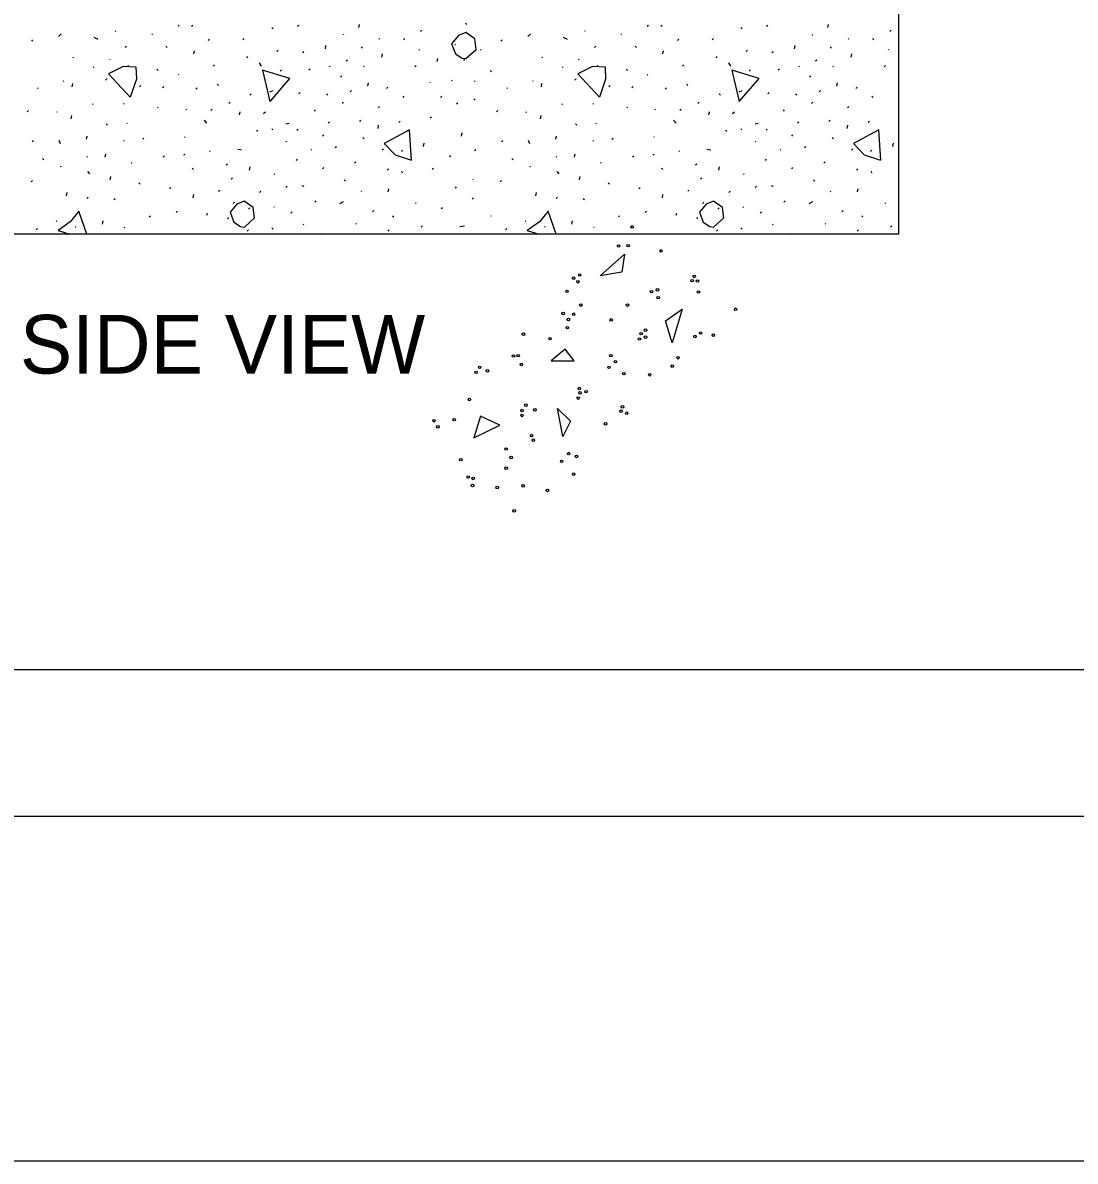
# Model space of a CAD drawing. Extents: x -120.7 to -50.3, y -20.2 to 3.8.
# Drawn here: x -68.476 to -64.887, y -20.241 to -16.36 of the extents above; entities that cross this region are included whole.
import ezdxf

# ---------------------------------------------------------------- set-up
doc = ezdxf.new("R2010")
doc.units = 0
for name, color, linetype in [('Default', 7, 'Continuous'), ('HATCH', 7, 'Continuous'), ('PR_Pattern_Area', 7, 'Continuous'), ('SHT_Plot_Shape_Full', 7, 'Continuous'), ('SHT_Plot_Shape_Half', 7, 'Continuous'), ('SHT_Sheet_Border', 7, 'Continuous'), ('TYP_Typical_Section_Linework', 7, 'Continuous'), ('TYP_Typical_Section_Txt', 7, 'Continuous')]:
    doc.layers.add(name, color=color, linetype=linetype)

# ---------------------------------------------------------------- blocks, each defined once
blk = doc.blocks.new('MCONC_1')
at = {"layer": 'Default'}
for points in [[(0.6469, 0.3145), (0.5681, 0.2555), (0.4697, 0.3244)], [(-0.5247, 0.2457), (-0.633, 0.1866), (-0.4853, 0.1374)], [(-0.0423, 0.1866), (0.0463, 0.0981), (0.0562, 0.1768)], [(-0.2884, -0.1479), (-0.1998, -0.02), (-0.1998, -0.1184)], [(0.6567, -0.1184), (0.4894, -0.2069), (0.5484, -0.0987)]]:
    blk.add_lwpolyline(points, close=True, dxfattribs=at)
for centre in [(-0.3736, 0.4299), (-0.3411, 0.4353), (-0.7283, 0.3677), (-0.7201, 0.4055), (-0.3248, 0.392), (-0.046, 0.3947), (0.2843, 0.392), (0.3601, 0.4164), (0.3629, 0.3866), (0.3953, 0.4055), (0.6553, 0.3677), (0.7798, 0.3893), (-0.6389, 0.3325), (-0.5035, 0.3514), (-0.1678, 0.3487), (-0.1489, 0.3325), (0.1842, 0.3217), (0.6932, 0.3325), (-0.1705, 0.2865), (0.038, 0.2757), (0.1463, 0.2513), (0.1815, 0.2784), (0.2221, 0.2784), (0.2843, 0.2865), (0.7988, 0.1864), (-0.7662, 0.1539), (-0.8041, 0.0592), (-0.3627, 0.089), (-0.3438, 0.1079), (-0.3086, 0.1133), (-0.2924, 0.0619), (0.3439, 0.1133), (0.463, 0.1079), (0.6065, 0.0673), (-0.8203, 0.0105), (-0.7905, 0.0348), (-0.5523, 0.0213), (0.6092, 0.0186), (0.6363, 0.0511), (-0.6254, -0.0517), (-0.5658, -0.0301), (-0.4142, -0.049), (-0.4034, -0.0247), (-0.0812, -0.0599), (-0.0541, -0.0463), (-0.0406, -0.0274), (-0.027, -0.0653), (0.1544, -0.0599), (0.2004, -0.0626), (0.2058, -0.022), (0.3791, -0.068), (0.4062, -0.0544), (0.436, -0.0572), (0.8042, -0.0463), (0.8231, -0.068), (0.8285, -0.0382), (-0.7337, -0.0923), (0.4089, -0.0842), (0.7852, -0.114), (-0.6281, -0.1843), (0.1869, -0.141), (-0.758, -0.2466), (-0.3871, -0.2384), (-0.3303, -0.2357), (0.2816, -0.2439), (-0.5523, -0.2953), (-0.3113, -0.2763), (-0.0758, -0.2628), (0.0325, -0.2736), (0.0461, -0.3034), (0.0542, -0.2628), (0.4008, -0.298), (0.4549, -0.2871), (0.6011, -0.2709), (0.6363, -0.279), (-0.3898, -0.3331), (0.6769, -0.3358), (0.861, -0.3223)]:
    blk.add_circle(centre, 0.00696, dxfattribs=at)

msp = doc.modelspace()

# ---------------------------------------------------------------- linework, layer by layer
at = {"layer": 'PR_Pattern_Area'}
for p, q in [((-67.9468, -16.3719), (-67.9424, -16.3675)), ((-67.9008, -16.3719), (-67.8964, -16.3675)), ((-67.6271, -16.3763), (-67.6227, -16.3807)), ((-67.5396, -16.3719), (-67.5352, -16.3675)), ((-67.3294, -16.3653), (-67.3316, -16.3762)), ((-66.966, -16.3609), (-66.9616, -16.3653)), ((-66.3468, -16.3719), (-66.3424, -16.3675)), ((-66.3008, -16.3719), (-66.2964, -16.3675)), ((-66.0271, -16.3763), (-66.0227, -16.3807)), ((-65.9396, -16.3719), (-65.9352, -16.3675)), ((-65.7294, -16.3653), (-65.7316, -16.3762)), ((-68.4457, -16.4222), (-68.4413, -16.4178)), ((-68.3538, -16.4069), (-68.3451, -16.3981)), ((-68.2334, -16.4091), (-68.2203, -16.4157)), ((-68.1591, -16.3872), (-68.1612, -16.3894)), ((-68.0343, -16.3981), (-68.0364, -16.4003)), ((-67.8439, -16.42), (-67.8395, -16.4156)), ((-67.7257, -16.4179), (-67.7213, -16.4135)), ((-67.382, -16.4003), (-67.3841, -16.4025)), ((-67.2594, -16.4135), (-67.2616, -16.4157)), ((-67.1784, -16.4135), (-67.174, -16.4179)), ((-67.1194, -16.3894), (-67.115, -16.385)), ((-66.8457, -16.4222), (-66.8413, -16.4178)), ((-66.7538, -16.4069), (-66.7451, -16.3981)), ((-66.6334, -16.4091), (-66.6203, -16.4157)), ((-66.5591, -16.3872), (-66.5612, -16.3894)), ((-66.4343, -16.3981), (-66.4364, -16.4003)), ((-66.2439, -16.42), (-66.2395, -16.4156)), ((-66.1257, -16.4179), (-66.1213, -16.4135)), ((-65.782, -16.4003), (-65.7841, -16.4025)), ((-65.6594, -16.4135), (-65.6616, -16.4157)), ((-65.5784, -16.4135), (-65.574, -16.4179)), ((-65.5194, -16.3894), (-65.515, -16.385)), ((-68.1263, -16.4441), (-68.1219, -16.4397)), ((-67.9882, -16.4397), (-67.9838, -16.4441)), ((-67.892, -16.455), (-67.8942, -16.4659)), ((-67.6097, -16.4573), (-67.6053, -16.4529)), ((-67.5221, -16.4616), (-67.5177, -16.4572)), ((-67.4433, -16.4375), (-67.4454, -16.4485)), ((-67.3228, -16.4419), (-67.3184, -16.4463)), ((-67.1237, -16.4507), (-67.1258, -16.4529)), ((-67.0011, -16.4332), (-67.0032, -16.4354)), ((-66.9136, -16.4507), (-66.9157, -16.4529)), ((-66.5263, -16.4441), (-66.5219, -16.4397)), ((-66.3882, -16.4397), (-66.3838, -16.4441)), ((-66.292, -16.455), (-66.2942, -16.4659)), ((-66.0097, -16.4573), (-66.0053, -16.4529)), ((-65.9221, -16.4616), (-65.9177, -16.4572)), ((-65.8433, -16.4375), (-65.8454, -16.4485)), ((-65.7228, -16.4419), (-65.7184, -16.4463)), ((-65.5237, -16.4507), (-65.5258, -16.4529)), ((-68.3036, -16.477), (-68.3057, -16.4792)), ((-68.1788, -16.4835), (-68.1809, -16.4857)), ((-67.7126, -16.4791), (-67.7082, -16.4747)), ((-67.3732, -16.4901), (-67.3688, -16.4857)), ((-67.2506, -16.466), (-67.2528, -16.4769)), ((-67.0624, -16.4813), (-67.0646, -16.4922)), ((-66.9727, -16.4879), (-66.9683, -16.4835)), ((-66.7036, -16.477), (-66.7057, -16.4792)), ((-66.5788, -16.4835), (-66.5809, -16.4857)), ((-66.1126, -16.4791), (-66.1082, -16.4747)), ((-65.7732, -16.4901), (-65.7688, -16.4857)), ((-65.6506, -16.466), (-65.6528, -16.4769)), ((-68.2335, -16.5098), (-68.2356, -16.512)), ((-68.1153, -16.5054), (-68.1174, -16.5076)), ((-68.0189, -16.5185), (-68.0145, -16.5229)), ((-67.8264, -16.5076), (-67.822, -16.5032)), ((-67.6621, -16.5076), (-67.6687, -16.4967)), ((-67.5986, -16.5251), (-67.5943, -16.5207)), ((-67.5002, -16.5207), (-67.4958, -16.5163)), ((-67.428, -16.5076), (-67.4301, -16.5098)), ((-67.312, -16.5076), (-67.3141, -16.5098)), ((-67.139, -16.5098), (-67.1346, -16.5054)), ((-66.8828, -16.5229), (-66.8784, -16.5273)), ((-66.6335, -16.5098), (-66.6356, -16.512)), ((-66.5153, -16.5054), (-66.5174, -16.5076)), ((-66.4189, -16.5185), (-66.4145, -16.5229)), ((-66.2264, -16.5076), (-66.222, -16.5032)), ((-66.0621, -16.5076), (-66.0687, -16.4967)), ((-65.9986, -16.5251), (-65.9943, -16.5207)), ((-65.9002, -16.5207), (-65.8958, -16.5163)), ((-65.828, -16.5076), (-65.8301, -16.5098)), ((-65.712, -16.5076), (-65.7141, -16.5098)), ((-65.539, -16.5098), (-65.5346, -16.5054)), ((-68.3364, -16.5579), (-68.3385, -16.5601)), ((-68.3079, -16.5777), (-68.3057, -16.5667)), ((-68.1941, -16.5557), (-68.1897, -16.5513)), ((-68.0781, -16.5777), (-68.0737, -16.5733)), ((-67.9446, -16.5361), (-67.9467, -16.5383)), ((-67.8132, -16.5689), (-67.8088, -16.5733)), ((-67.393, -16.5448), (-67.3886, -16.5404)), ((-67.2988, -16.5645), (-67.301, -16.5754)), ((-67.0865, -16.5623), (-67.0886, -16.5645)), ((-67.012, -16.5558), (-67.0142, -16.558)), ((-66.9332, -16.5579), (-66.9354, -16.5601)), ((-66.7364, -16.5579), (-66.7385, -16.5601)), ((-66.7079, -16.5777), (-66.7057, -16.5667)), ((-66.5941, -16.5557), (-66.5897, -16.5513)), ((-66.4781, -16.5777), (-66.4737, -16.5733)), ((-66.3446, -16.5361), (-66.3467, -16.5383)), ((-66.2132, -16.5689), (-66.2088, -16.5733)), ((-65.793, -16.5448), (-65.7886, -16.5404)), ((-65.6988, -16.5645), (-65.701, -16.5754)), ((-68.4238, -16.5821), (-68.426, -16.5843)), ((-67.9993, -16.582), (-67.9949, -16.5776)), ((-67.8855, -16.5864), (-67.8811, -16.582)), ((-67.7015, -16.6017), (-67.6971, -16.6061)), ((-67.6337, -16.5951), (-67.6227, -16.5908)), ((-67.5352, -16.6017), (-67.5308, -16.5973)), ((-67.441, -16.6017), (-67.4366, -16.6061)), ((-67.3601, -16.5951), (-67.3557, -16.5907)), ((-67.2354, -16.5842), (-67.231, -16.5798)), ((-67.1806, -16.6105), (-67.1762, -16.6149)), ((-67.0515, -16.6149), (-67.0471, -16.6105)), ((-66.8238, -16.5821), (-66.826, -16.5843)), ((-66.3993, -16.582), (-66.3949, -16.5776)), ((-66.2855, -16.5864), (-66.2811, -16.582)), ((-66.1015, -16.6017), (-66.0971, -16.6061)), ((-66.0337, -16.5951), (-66.0227, -16.5908)), ((-65.9352, -16.6017), (-65.9308, -16.5973)), ((-65.841, -16.6017), (-65.8366, -16.6061)), ((-65.7601, -16.5951), (-65.7557, -16.5907)), ((-65.6354, -16.5842), (-65.631, -16.5798)), ((-65.5806, -16.6105), (-65.5762, -16.6149)), ((-68.2357, -16.6367), (-68.2378, -16.6389)), ((-68.1306, -16.6346), (-68.1328, -16.6368)), ((-68.0146, -16.6477), (-68.0168, -16.6499)), ((-67.7738, -16.6345), (-67.7694, -16.6301)), ((-67.3864, -16.6345), (-67.382, -16.6301)), ((-67.2638, -16.6499), (-67.2594, -16.6455)), ((-66.9968, -16.6367), (-66.9924, -16.6323)), ((-66.9376, -16.6192), (-66.9332, -16.6236)), ((-66.6357, -16.6367), (-66.6378, -16.6389)), ((-66.5306, -16.6346), (-66.5328, -16.6368)), ((-66.4146, -16.6477), (-66.4168, -16.6499)), ((-66.1738, -16.6345), (-66.1694, -16.6301)), ((-65.7864, -16.6345), (-65.782, -16.6301)), ((-65.6638, -16.6499), (-65.6594, -16.6455)), ((-68.461, -16.663), (-68.4566, -16.6586)), ((-68.3583, -16.663), (-68.3604, -16.6652)), ((-68.3101, -16.6761), (-68.3122, -16.6871)), ((-67.9183, -16.6543), (-67.9204, -16.6565)), ((-67.8352, -16.6586), (-67.8308, -16.6542)), ((-67.7366, -16.6739), (-67.7344, -16.663)), ((-67.6556, -16.6696), (-67.649, -16.663)), ((-67.4827, -16.6608), (-67.4783, -16.6564)), ((-67.0865, -16.6849), (-67.0821, -16.6805)), ((-66.861, -16.663), (-66.8566, -16.6586)), ((-66.7583, -16.663), (-66.7604, -16.6652)), ((-66.7101, -16.6761), (-66.7122, -16.6871)), ((-66.3183, -16.6543), (-66.3204, -16.6565)), ((-66.2352, -16.6586), (-66.2308, -16.6542)), ((-66.1366, -16.6739), (-66.1344, -16.663)), ((-66.0556, -16.6696), (-66.049, -16.663)), ((-65.8827, -16.6608), (-65.8783, -16.6564)), ((-68.1918, -16.7046), (-68.1874, -16.709)), ((-68.1197, -16.7024), (-68.1218, -16.7046)), ((-67.8482, -16.7024), (-67.857, -16.6915)), ((-67.6796, -16.7265), (-67.6752, -16.7309)), ((-67.6271, -16.7199), (-67.6249, -16.7243)), ((-67.579, -16.7046), (-67.568, -16.7024)), ((-67.5418, -16.7265), (-67.5374, -16.7221)), ((-67.4346, -16.7024), (-67.4302, -16.698)), ((-67.3273, -16.6959), (-67.3229, -16.6915)), ((-67.2638, -16.7089), (-67.2659, -16.7199)), ((-67.1938, -16.7002), (-67.1894, -16.6958)), ((-66.5918, -16.7046), (-66.5874, -16.709)), ((-66.5197, -16.7024), (-66.5218, -16.7046)), ((-66.2482, -16.7024), (-66.257, -16.6915)), ((-66.0796, -16.7265), (-66.0752, -16.7309)), ((-66.0271, -16.7199), (-66.0249, -16.7243)), ((-65.979, -16.7046), (-65.968, -16.7024)), ((-65.9418, -16.7265), (-65.9374, -16.7221)), ((-65.8346, -16.7024), (-65.8302, -16.698)), ((-65.7273, -16.6959), (-65.7229, -16.6915)), ((-65.6638, -16.7089), (-65.6659, -16.7199)), ((-65.5938, -16.7002), (-65.5894, -16.6958)), ((-68.4435, -16.7659), (-68.4391, -16.7615)), ((-68.3472, -16.7724), (-68.3516, -16.7615)), ((-68.2576, -16.7461), (-68.2597, -16.7571)), ((-68.1306, -16.7615), (-68.1328, -16.7637)), ((-68.0672, -16.7571), (-68.0628, -16.7527)), ((-67.9227, -16.7484), (-67.9248, -16.7506)), ((-67.5768, -16.7659), (-67.579, -16.7637)), ((-67.4542, -16.7462), (-67.4498, -16.7418)), ((-67.3163, -16.7506), (-67.3119, -16.755)), ((-66.9792, -16.7353), (-66.9813, -16.7462)), ((-66.8435, -16.7659), (-66.8391, -16.7615)), ((-66.7472, -16.7724), (-66.7516, -16.7615)), ((-66.6576, -16.7461), (-66.6597, -16.7571)), ((-66.5306, -16.7615), (-66.5328, -16.7637)), ((-66.4672, -16.7571), (-66.4628, -16.7527)), ((-66.3227, -16.7484), (-66.3248, -16.7506)), ((-65.9768, -16.7659), (-65.979, -16.7637)), ((-65.8542, -16.7462), (-65.8498, -16.7418)), ((-65.7163, -16.7506), (-65.7119, -16.755)), ((-67.8373, -16.7965), (-67.8394, -16.7987)), ((-67.73, -16.7943), (-67.7431, -16.7921)), ((-67.4914, -16.7922), (-67.4936, -16.7944)), ((-67.4105, -16.7856), (-67.4061, -16.7812)), ((-67.2507, -16.7943), (-67.2463, -16.7899)), ((-67.185, -16.7987), (-67.1806, -16.7943)), ((-67.1084, -16.7703), (-67.1105, -16.7812)), ((-66.9354, -16.7965), (-66.931, -16.7921)), ((-66.2373, -16.7965), (-66.2394, -16.7987)), ((-66.13, -16.7943), (-66.1431, -16.7921)), ((-65.8914, -16.7922), (-65.8936, -16.7944)), ((-65.8105, -16.7856), (-65.8061, -16.7812)), ((-65.6507, -16.7943), (-65.6463, -16.7899)), ((-65.585, -16.7987), (-65.5806, -16.7943)), ((-65.5084, -16.7703), (-65.5105, -16.7812)), ((-68.4084, -16.8228), (-68.404, -16.8272)), ((-68.2554, -16.8163), (-68.2575, -16.8185)), ((-68.1941, -16.8075), (-68.1962, -16.8184)), ((-68.1044, -16.8359), (-68.1065, -16.8381)), ((-67.9971, -16.8184), (-67.9927, -16.814)), ((-67.927, -16.8097), (-67.9226, -16.8075)), ((-67.7826, -16.8447), (-67.7782, -16.8403)), ((-67.544, -16.8294), (-67.5396, -16.825)), ((-67.3448, -16.8381), (-67.3404, -16.8337)), ((-67.0207, -16.8119), (-67.0163, -16.8163)), ((-66.8084, -16.8228), (-66.804, -16.8272)), ((-66.6554, -16.8163), (-66.6575, -16.8185)), ((-66.5941, -16.8075), (-66.5962, -16.8184)), ((-66.5044, -16.8359), (-66.5065, -16.8381)), ((-66.3971, -16.8184), (-66.3927, -16.814)), ((-66.327, -16.8097), (-66.3226, -16.8075)), ((-66.1826, -16.8447), (-66.1782, -16.8403)), ((-65.944, -16.8294), (-65.9396, -16.825)), ((-65.7448, -16.8381), (-65.7404, -16.8337)), ((-68.3452, -16.8491), (-68.3473, -16.8513)), ((-68.2554, -16.8666), (-68.2488, -16.8753)), ((-68.1766, -16.8841), (-68.1787, -16.895)), ((-67.8985, -16.8557), (-67.8941, -16.8601)), ((-67.7016, -16.8512), (-67.7037, -16.8621)), ((-67.6162, -16.8753), (-67.6184, -16.8775)), ((-67.4542, -16.8578), (-67.4498, -16.8534)), ((-67.2332, -16.8622), (-67.2288, -16.8578)), ((-67.1849, -16.8666), (-67.1805, -16.871)), ((-67.08, -16.86), (-67.0756, -16.8556)), ((-66.7452, -16.8491), (-66.7473, -16.8513)), ((-66.6554, -16.8666), (-66.6488, -16.8753)), ((-66.5766, -16.8841), (-66.5787, -16.895)), ((-66.2985, -16.8557), (-66.2941, -16.8601)), ((-66.1016, -16.8512), (-66.1037, -16.8621)), ((-66.0162, -16.8753), (-66.0184, -16.8775)), ((-65.8542, -16.8578), (-65.8498, -16.8534)), ((-65.6332, -16.8622), (-65.6288, -16.8578)), ((-65.5849, -16.8666), (-65.5805, -16.871)), ((-68.4479, -16.9016), (-68.4435, -16.8972)), ((-68.0802, -16.906), (-68.0758, -16.9104)), ((-67.9752, -16.9257), (-67.9708, -16.9213)), ((-67.7651, -16.8929), (-67.7607, -16.8885)), ((-67.579, -16.9213), (-67.5746, -16.9169)), ((-67.5242, -16.9147), (-67.5176, -16.9169)), ((-67.3798, -16.8951), (-67.3754, -16.8995)), ((-67.0011, -16.9235), (-66.9967, -16.9191)), ((-66.9398, -16.8929), (-66.942, -16.8951)), ((-66.8479, -16.9016), (-66.8435, -16.8972)), ((-66.4802, -16.906), (-66.4758, -16.9104)), ((-66.3752, -16.9257), (-66.3708, -16.9213)), ((-66.1651, -16.8929), (-66.1607, -16.8885)), ((-65.979, -16.9213), (-65.9746, -16.9169)), ((-65.9242, -16.9147), (-65.9176, -16.9169)), ((-65.7798, -16.8951), (-65.7754, -16.8995)), ((-68.3254, -16.9388), (-68.3276, -16.9497)), ((-68.2575, -16.9585), (-68.2531, -16.9541)), ((-68.1656, -16.9585), (-68.1612, -16.9629)), ((-67.8942, -16.9453), (-67.8964, -16.9563)), ((-67.8089, -16.9345), (-67.8045, -16.9301)), ((-67.6688, -16.9388), (-67.6644, -16.9344)), ((-67.3207, -16.9345), (-67.3228, -16.9367)), ((-67.2288, -16.9257), (-67.2309, -16.9366)), ((-66.9442, -16.9563), (-66.9398, -16.9607)), ((-66.7254, -16.9388), (-66.7276, -16.9497)), ((-66.6575, -16.9585), (-66.6531, -16.9541)), ((-66.5656, -16.9585), (-66.5612, -16.9629)), ((-66.2942, -16.9453), (-66.2964, -16.9563)), ((-66.2089, -16.9345), (-66.2045, -16.9301)), ((-66.0688, -16.9388), (-66.0644, -16.9344)), ((-65.7207, -16.9345), (-65.7228, -16.9367)), ((-65.6288, -16.9257), (-65.6309, -16.9366)), ((-67.7585, -16.9761), (-67.7541, -16.9717)), ((-67.706, -16.9957), (-67.7016, -16.9913)), ((-67.6184, -16.987), (-67.6206, -16.9892)), ((-67.4805, -16.9717), (-67.4761, -16.9673)), ((-67.3951, -16.9761), (-67.382, -16.9695)), ((-67.2835, -17.0045), (-67.2791, -17.0001)), ((-67.1346, -16.9739), (-67.1368, -16.9761)), ((-67.0493, -16.9936), (-67.0449, -16.9892)), ((-66.1585, -16.9761), (-66.1541, -16.9717)), ((-66.106, -16.9957), (-66.1016, -16.9913)), ((-66.0184, -16.987), (-66.0206, -16.9892)), ((-65.8805, -16.9717), (-65.8761, -16.9673)), ((-65.7951, -16.9761), (-65.782, -16.9695)), ((-65.6835, -17.0045), (-65.6791, -17.0001)), ((-65.5346, -16.9739), (-65.5368, -16.9761)), ((-68.3605, -17.0351), (-68.3626, -17.0373)), ((-68.2028, -17.0351), (-68.205, -17.0461)), ((-68.0453, -17.022), (-68.0409, -17.0176)), ((-67.9534, -17.0067), (-67.949, -17.0023)), ((-67.8482, -17.0155), (-67.846, -17.0089)), ((-67.7782, -17.0286), (-67.7738, -17.0242)), ((-67.5615, -17.0089), (-67.5571, -17.0045)), ((-67.2156, -17.0176), (-67.2112, -17.022)), ((-66.8785, -17.0177), (-66.8806, -17.0199)), ((-66.7605, -17.0351), (-66.7626, -17.0373)), ((-66.6028, -17.0351), (-66.605, -17.0461)), ((-66.4453, -17.022), (-66.4409, -17.0176)), ((-66.3534, -17.0067), (-66.349, -17.0023)), ((-66.2482, -17.0155), (-66.246, -17.0089)), ((-66.1782, -17.0286), (-66.1738, -17.0242)), ((-65.9615, -17.0089), (-65.9571, -17.0045)), ((-65.6156, -17.0176), (-65.6112, -17.022)), ((-68.4304, -17.0658), (-68.426, -17.0614)), ((-68.2948, -17.0549), (-68.297, -17.0571)), ((-68.1284, -17.0571), (-68.1306, -17.0593)), ((-67.7104, -17.0701), (-67.706, -17.0657)), ((-67.6271, -17.0592), (-67.6227, -17.0636)), ((-67.5177, -17.0461), (-67.5198, -17.0483)), ((-67.3382, -17.0439), (-67.3404, -17.0461)), ((-67.231, -17.0701), (-67.2266, -17.0657)), ((-67.1172, -17.057), (-67.1128, -17.0526)), ((-66.9857, -17.0549), (-66.9704, -17.0527)), ((-66.8304, -17.0658), (-66.826, -17.0614)), ((-66.6948, -17.0549), (-66.697, -17.0571)), ((-66.5284, -17.0571), (-66.5306, -17.0593)), ((-66.1104, -17.0701), (-66.106, -17.0657)), ((-66.0271, -17.0592), (-66.0227, -17.0636)), ((-65.9177, -17.0461), (-65.9198, -17.0483)), ((-65.7382, -17.0439), (-65.7404, -17.0461)), ((-65.631, -17.0701), (-65.6266, -17.0657)), ((-65.5172, -17.057), (-65.5128, -17.0526)), ((-67.4584, -17.0809), (-67.4564, -17.0789)), ((-65.8584, -17.0809), (-65.8564, -17.0789))]:
    msp.add_line(p, q, dxfattribs=at)
for points in [[(-66.9652, -16.4821), (-66.9306, -16.4511), (-66.9349, -16.4151), (-66.9659, -16.3934), (-66.9909, -16.4037), (-67.0137, -16.4311), (-67.0008, -16.4661), (-66.9784, -16.48), (-66.9659, -16.4821)], [(-68.1085, -16.6127), (-68.0876, -16.5505), (-68.0889, -16.5117), (-68.1336, -16.5086), (-68.1838, -16.5335), (-68.1094, -16.6133)], [(-67.6328, -16.6278), (-67.5654, -16.5501), (-67.6585, -16.5216), (-67.6339, -16.6278)], [(-66.5085, -16.6127), (-66.4876, -16.5505), (-66.4889, -16.5117), (-66.5336, -16.5086), (-66.5838, -16.5335), (-66.5094, -16.6133)], [(-66.0328, -16.6278), (-65.9654, -16.5501), (-66.0585, -16.5216), (-66.0339, -16.6278)], [(-67.1502, -16.8279), (-67.1574, -16.7253), (-67.2434, -16.771), (-67.2067, -16.8099), (-67.151, -16.8287)], [(-65.5502, -16.8279), (-65.5574, -16.7253), (-65.6434, -16.771), (-65.6067, -16.8099), (-65.551, -16.8287)], [(-67.7206, -17.0562), (-67.686, -17.0252), (-67.6903, -16.9892), (-67.7213, -16.9675), (-67.7463, -16.9778), (-67.7691, -17.0052), (-67.7562, -17.0401), (-67.7338, -17.0541), (-67.7213, -17.0562)], [(-66.1206, -17.0562), (-66.086, -17.0252), (-66.0903, -16.9892), (-66.1213, -16.9675), (-66.1463, -16.9778), (-66.1691, -17.0052), (-66.1562, -17.0401), (-66.1338, -17.0541), (-66.1213, -17.0562)], [(-68.2575, -17.0809), (-68.2846, -17.0023), (-68.3141, -17.0382), (-68.3558, -17.0686), (-68.3156, -17.0809)], [(-66.6575, -17.0809), (-66.6846, -17.0023), (-66.7141, -17.0382), (-66.7558, -17.0686), (-66.7156, -17.0809)]]:
    msp.add_lwpolyline(points, dxfattribs=at)
at = {"layer": 'SHT_Plot_Shape_Full'}
msp.add_lwpolyline([(-86.2592, 3.7586), (-50.2592, 3.7586), (-50.2592, -20.2414), (-86.2592, -20.2414)], close=True, dxfattribs=at)
at = {"layer": 'SHT_Plot_Shape_Half'}
msp.add_lwpolyline([(-84.6217, 2.9337), (-50.6217, 2.9337), (-50.6217, -19.0663), (-84.6217, -19.0663)], close=True, dxfattribs=at)
at = {"layer": 'SHT_Sheet_Border'}
msp.add_lwpolyline([(-51.1717, -18.5663), (-82.6717, -18.5663), (-82.6717, 2.4337), (-51.1717, 2.4337)], close=True, dxfattribs=at)
at = {"layer": 'TYP_Typical_Section_Linework'}
for q in [(-65.4886, -11.0809), (-69.9886, -17.0809)]:
    msp.add_line((-65.4886, -17.0809), q, dxfattribs=at)

# ---------------------------------------------------------------- block references
at = {"layer": 'HATCH', "xscale": 0.6299200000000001, "yscale": 0.6299200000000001, "rotation": 44.99999999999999}
msp.add_blockref('MCONC_1', (-66.5725, -17.5766), dxfattribs=at)

# ---------------------------------------------------------------- texts
at = {"layer": 'TYP_Typical_Section_Txt'}
msp.add_text('SIDE VIEW', height=0.2, dxfattribs=at).set_placement((-68.486, -17.5558))

doc.saveas('drawing.dxf')
